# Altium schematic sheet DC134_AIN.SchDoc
size 431 x 279 mm; Date: Not shown in title block; ApprovedBy: Not shown in title block; CheckedBy: Not shown in title block; Author: Not shown in title block; CompanyName: Not shown in title block; Engineer: Not shown in title block; Organization: Not shown in title block; Address1: Not shown in title block; Address2: Not shown in title block; Address3: Not shown in title block; Address4: Not shown in title block; DocumentNumber: 2; Revision: Use project parameter SCH_Rev; SheetNumber: 2; SheetTotal: 9; PageSetup: Record=PageOptions¦CenterHorizontal=True¦CenterVertical=True¦PrintScale=1.00¦XCorrection=1.00¦YCorrection=1.00¦PrintKind=0¦BorderSize=5000000¦LeftOffset=0¦BottomOffset=0¦Orientation=2¦PaperLength=1000¦PaperWidth=1000¦Scale=100¦PaperSource=15¦PrintQuality=600¦MediaType=1¦DitherType=10¦PaperKind=Letter¦PrintScaleMode=1
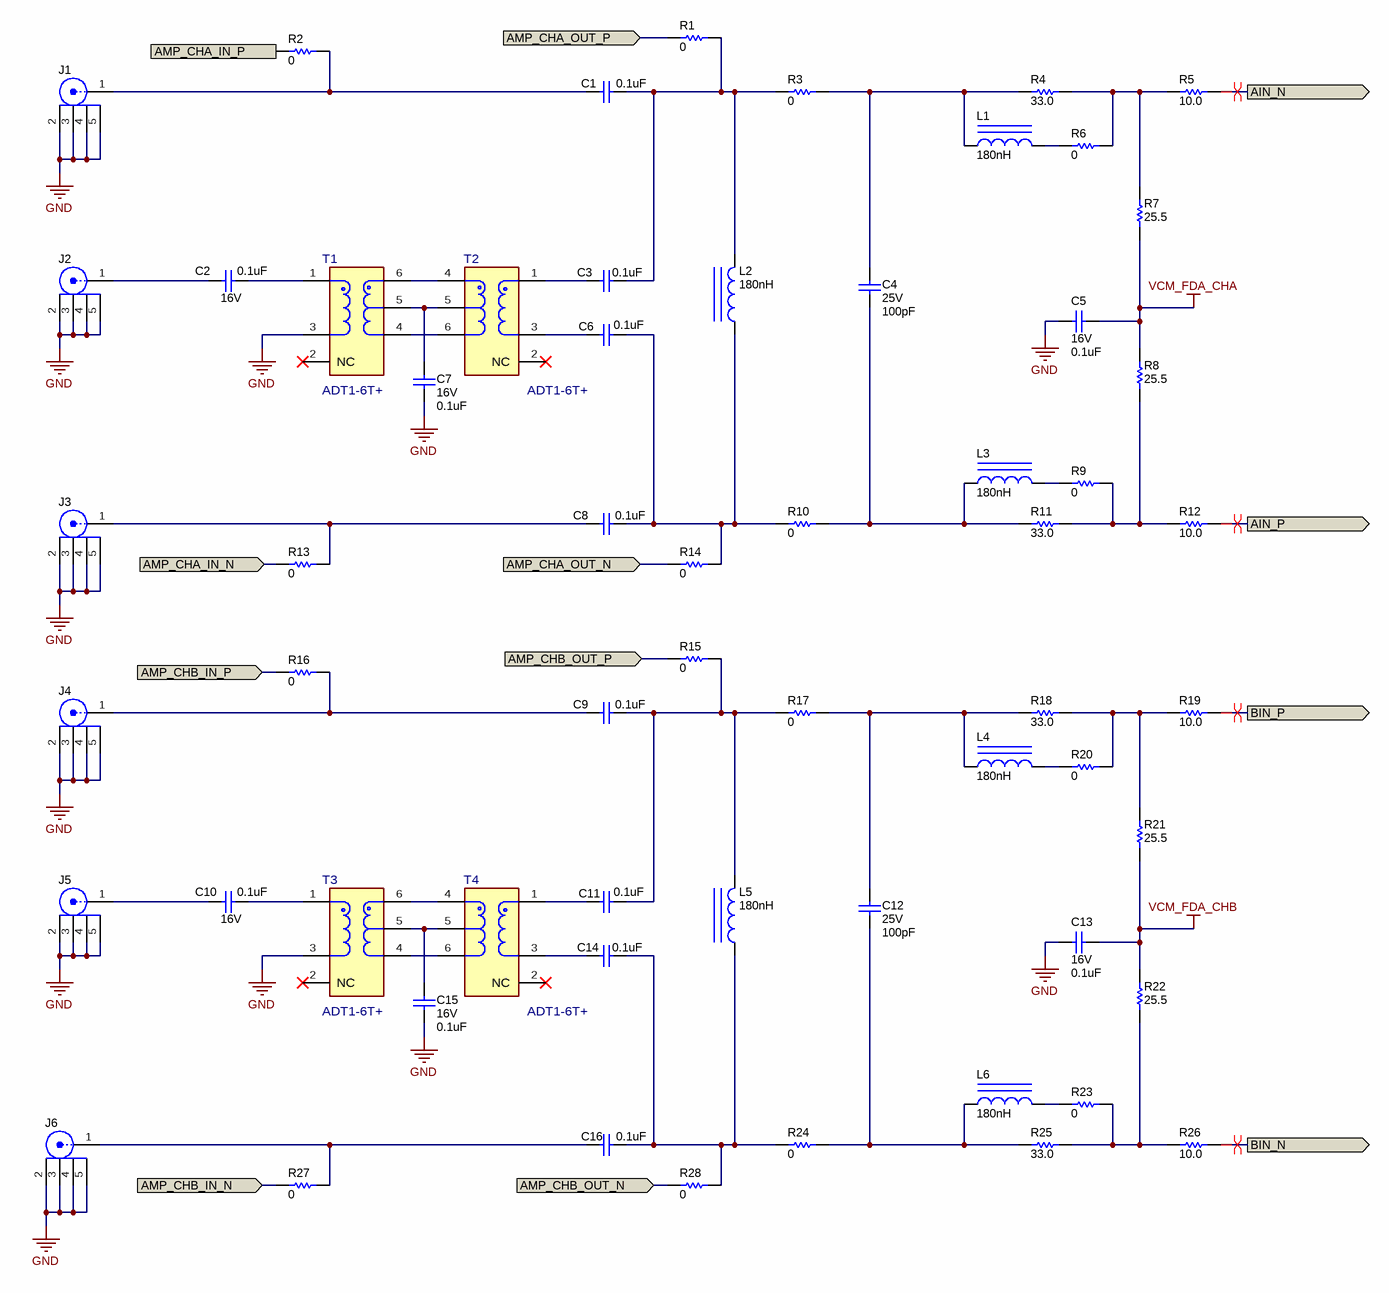
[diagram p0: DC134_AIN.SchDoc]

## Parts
C1  ValueDisplayed: 0.1uF  [0201L]  (hidden comment: GRM033Z71C104KE14D)
C2  VDC_V: 16V  ValueDisplayed: 0.1uF  [0201L]  (hidden comment: GRM033Z71C104KE14D)
C3  ValueDisplayed: 0.1uF  [0201L]  (hidden comment: GRM033Z71C104KE14D)
C4  VDC_V: 25V  ValueDisplayed: 100pF  [0201]  (hidden comment: GRM033R71E101KA01D)
C5  VDC_V: 16V  ValueDisplayed: 0.1uF  [0201L]  (hidden comment: GRM033Z71C104KE14D)
C6  ValueDisplayed: 0.1uF  [0201L]  (hidden comment: GRM033Z71C104KE14D)
C7  VDC_V: 16V  ValueDisplayed: 0.1uF  [0201L]  (hidden comment: GRM033Z71C104KE14D)
C8  ValueDisplayed: 0.1uF  [0201L]  (hidden comment: GRM033Z71C104KE14D)
C9  ValueDisplayed: 0.1uF  [0201L]  (hidden comment: GRM033Z71C104KE14D)
C10  VDC_V: 16V  ValueDisplayed: 0.1uF  [0201L]  (hidden comment: GRM033Z71C104KE14D)
C11  ValueDisplayed: 0.1uF  [0201L]  (hidden comment: GRM033Z71C104KE14D)
C12  VDC_V: 25V  ValueDisplayed: 100pF  [0201]  (hidden comment: GRM033R71E101KA01D)
C13  VDC_V: 16V  ValueDisplayed: 0.1uF  [0201L]  (hidden comment: GRM033Z71C104KE14D)
C14  ValueDisplayed: 0.1uF  [0201L]  (hidden comment: GRM033Z71C104KE14D)
C15  VDC_V: 16V  ValueDisplayed: 0.1uF  [0201L]  (hidden comment: GRM033Z71C104KE14D)
C16  ValueDisplayed: 0.1uF  [0201L]  (hidden comment: GRM033Z71C104KE14D)
J1  142-0701-801  [Johnson_142-0701-801]  (value not drawn)
J2  901-144-8RFX  [AMPHENOL_901-144-8RFX]  (value not drawn)
J3  142-0701-801  [Johnson_142-0701-801]  (value not drawn)
J4  142-0701-801  [Johnson_142-0701-801]  (value not drawn)
J5  901-144-8RFX  [AMPHENOL_901-144-8RFX]  (value not drawn)
J6  142-0701-801  [Johnson_142-0701-801]  (value not drawn)
L1  ValueDisplayed: 180nH  [IND_LQG15H]  (hidden comment: LQG15HSR18J02D)
L2  ValueDisplayed: 180nH  [IND_LQG15H]  (hidden comment: LQG15HSR18J02D)
L3  ValueDisplayed: 180nH  [IND_LQG15H]  (hidden comment: LQG15HSR18J02D)
L4  ValueDisplayed: 180nH  [IND_LQG15H]  (hidden comment: LQG15HSR18J02D)
L5  ValueDisplayed: 180nH  [IND_LQG15H]  (hidden comment: LQG15HSR18J02D)
L6  ValueDisplayed: 180nH  [IND_LQG15H]  (hidden comment: LQG15HSR18J02D)
R1  ValueDisplayed: 0  [0201L]  (hidden comment: CRCW02010000Z0ED)
R2  ValueDisplayed: 0  [0201L]  (hidden comment: CRCW02010000Z0ED)
R3  ValueDisplayed: 0  [0402]  (hidden comment: RC0402JR-070RL)
R4  ValueDisplayed: 33.0  [0201]  (hidden comment: RC0201FR-7D33RL)
R5  ValueDisplayed: 10.0  [0201]  (hidden comment: RC0201FR-7D10RL)
R6  ValueDisplayed: 0  [0201L]  (hidden comment: CRCW02010000Z0ED)
R7  ValueDisplayed: 25.5  [0201L]  (hidden comment: RC0201FR-0725R5L)
R8  ValueDisplayed: 25.5  [0201L]  (hidden comment: RC0201FR-0725R5L)
R9  ValueDisplayed: 0  [0201L]  (hidden comment: CRCW02010000Z0ED)
R10  ValueDisplayed: 0  [0402]  (hidden comment: RC0402JR-070RL)
R11  ValueDisplayed: 33.0  [0201]  (hidden comment: RC0201FR-7D33RL)
R12  ValueDisplayed: 10.0  [0201]  (hidden comment: RC0201FR-7D10RL)
R13  ValueDisplayed: 0  [0201L]  (hidden comment: CRCW02010000Z0ED)
R14  ValueDisplayed: 0  [0201L]  (hidden comment: CRCW02010000Z0ED)
R15  ValueDisplayed: 0  [0201L]  (hidden comment: CRCW02010000Z0ED)
R16  ValueDisplayed: 0  [0201L]  (hidden comment: CRCW02010000Z0ED)
R17  ValueDisplayed: 0  [0402]  (hidden comment: RC0402JR-070RL)
R18  ValueDisplayed: 33.0  [0201]  (hidden comment: RC0201FR-7D33RL)
R19  ValueDisplayed: 10.0  [0201]  (hidden comment: RC0201FR-7D10RL)
R20  ValueDisplayed: 0  [0201L]  (hidden comment: CRCW02010000Z0ED)
R21  ValueDisplayed: 25.5  [0201L]  (hidden comment: RC0201FR-0725R5L)
R22  ValueDisplayed: 25.5  [0201L]  (hidden comment: RC0201FR-0725R5L)
R23  ValueDisplayed: 0  [0201L]  (hidden comment: CRCW02010000Z0ED)
R24  ValueDisplayed: 0  [0402]  (hidden comment: RC0402JR-070RL)
R25  ValueDisplayed: 33.0  [0201]  (hidden comment: RC0201FR-7D33RL)
R26  ValueDisplayed: 10.0  [0201]  (hidden comment: RC0201FR-7D10RL)
R27  ValueDisplayed: 0  [0201L]  (hidden comment: CRCW02010000Z0ED)
R28  ValueDisplayed: 0  [0201L]  (hidden comment: CRCW02010000Z0ED)
T1  ADT1-6T+  [FP-ADT1-6T+_SMD6-MFG]  (value not drawn)
T2  ADT1-6T+  [FP-ADT1-6T+_SMD6-MFG]  (value not drawn)
T3  ADT1-6T+  [FP-ADT1-6T+_SMD6-MFG]  (value not drawn)
T4  ADT1-6T+  [FP-ADT1-6T+_SMD6-MFG]  (value not drawn)

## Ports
AIN_N (out), AIN_P (out), AMP_CHA_IN_N (in), AMP_CHA_IN_P (in), AMP_CHA_OUT_N (in), AMP_CHA_OUT_P (in), AMP_CHB_IN_N (in), AMP_CHB_IN_P (in), AMP_CHB_OUT_N (in), AMP_CHB_OUT_P (in), BIN_N (out), BIN_P (out)

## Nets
GND: C5.1 C7.1 C13.1 C15.1 J1.2 J1.3 J1.4 J1.5 J2.2 J2.3 J2.4 J2.5 J3.2 J3.3 J3.4 J3.5 J4.2 J4.3 J4.4 J4.5 J5.2 J5.3 J5.4 J5.5 J6.2 J6.3 J6.4 J6.5 T1.3 T3.3
VCM_FDA_CHA: C5.2 R7.1 R8.2
VCM_FDA_CHB: C13.2 R21.1 R22.2
AIN_N: R5.2 ; port AIN_N
AIN_P: R12.2 ; port AIN_P
AMP_CHA_IN_N: R13.1 ; port AMP_CHA_IN_N
AMP_CHA_IN_P: R2.1 ; port AMP_CHA_IN_P
AMP_CHA_OUT_N: R14.1 ; port AMP_CHA_OUT_N
AMP_CHA_OUT_P: R1.1 ; port AMP_CHA_OUT_P
AMP_CHB_IN_N: R27.1 ; port AMP_CHB_IN_N
AMP_CHB_IN_P: R16.1 ; port AMP_CHB_IN_P
AMP_CHB_OUT_N: R28.1 ; port AMP_CHB_OUT_N
AMP_CHB_OUT_P: R15.1 ; port AMP_CHB_OUT_P
BIN_N: R26.2 ; port BIN_N
BIN_P: R19.2 ; port BIN_P
NetC1_1: C1.1 J1.1 R2.2
NetC1_2: C1.2 C3.2 L2.2 R1.2 R3.1
NetC2_1: C2.1 J2.1
NetC2_2: C2.2 T1.1
NetC3_1: C3.1 T2.1
NetC4_1: C4.1 L1.1 R3.2 R4.1
NetC4_2: C4.2 L3.1 R10.2 R11.1
NetC6_1: C6.1 T2.3
NetC6_2: C6.2 C8.2 L2.1 R10.1 R14.2
NetC7_2: C7.2 T1.5 T2.5
NetC8_1: C8.1 J3.1 R13.2
NetC9_1: C9.1 J4.1 R16.2
NetC9_2: C9.2 C11.2 L5.2 R15.2 R17.1
NetC10_1: C10.1 J5.1
NetC10_2: C10.2 T3.1
NetC11_1: C11.1 T4.1
NetC12_1: C12.1 L4.1 R17.2 R18.1
NetC12_2: C12.2 L6.1 R24.2 R25.1
NetC14_1: C14.1 T4.3
NetC14_2: C14.2 C16.2 L5.1 R24.1 R28.2
NetC15_2: C15.2 T3.5 T4.5
NetC16_1: C16.1 J6.1 R27.2
NetL1_2: L1.2 R6.1
NetL3_2: L3.2 R9.1
NetL4_2: L4.2 R20.1
NetL6_2: L6.2 R23.1
NetR4_2: R4.2 R5.1 R6.2 R7.2
NetR8_1: R8.1 R9.2 R11.2 R12.1
NetR18_2: R18.2 R19.1 R20.2 R21.2
NetR22_1: R22.1 R23.2 R25.2 R26.1
NetT1_4: T1.4 T2.6
NetT1_6: T1.6 T2.4
NetT3_4: T3.4 T4.6
NetT3_6: T3.6 T4.4

Not connected (* = marked no-connect by the designer): T1 2(NC)*; T2 2(NC)*; T3 2(NC)*; T4 2(NC)*

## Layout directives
differential pair: AIN_N, AIN_P, BIN_N, BIN_P

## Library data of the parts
C1 C3 C6 C8 C9 C11 C14 C16 = CMP-0064970-1: CAP, CERM, 0.1 uF, 16 V,+/- 10%, X7R, 0201; Manufacturer: MuRata; TaMin_C: -55°C; Polarized: N; SizeAreaWB_mm2: 2.08; Value1: Unknown; U/M: EA; Value: 0.1uF; TaMax_C: 125°C; SizeZ_mm: 0.26; SizeX_mm: 0.6; SizeY_mm: 0.3; Cap_Case: 0201; Value2: 16V; SizeArea_mm2: 0.18; CompType: Capacitor; Cap_F: 100nF; AEC Category: Q200
C2 C5 C7 C10 C13 C15 = CMP-0064970-1: CAP, CERM, 0.1 uF, 16 V,+/- 10%, X7R, 0201; Manufacturer: MuRata; TaMin_C: -55°C; Polarized: N; SizeAreaWB_mm2: 2.08; Value1: Unknown; U/M: EA; Value: 0.1uF; TaMax_C: 125°C; SizeZ_mm: 0.26; SizeX_mm: 0.6; SizeY_mm: 0.3; Cap_Case: 0201; SizeArea_mm2: 0.18; CompType: Capacitor; Cap_F: 100nF; AEC Category: Q200
C4 C12 = CMP-0009763-1: CAP, CERM, 100 pF, 25 V, +/- 10%, X7R, 0201; Manufacturer: MuRata; TaMin_C: -55°C; Polarized: N; SizeAreaWB_mm2: 2.08; Value1: Unknown; U/M: EA; Value: 100pF; TaMax_C: 125°C; SizeZ_mm: 0.26; SizeX_mm: 0.6; SizeY_mm: 0.3; SizeArea_mm2: 0.18; AEC Category: Q200
J1 J3 J4 J6 = CMP-0055828-1: Connector, End launch SMA, 50 ohm, SMT; Manufacturer: Cinch Connectivity; CNHeader: FALSE; Green_Lifecycle: Not Set; Green_REACh: Incomplete; CT: TRUE
J2 J5 = CMP-0055833-1: SMA Straight Jack, Gold, 50 Ohm, TH; Manufacturer: Amphenol RF; CNHeader: FALSE; Green_Lifecycle: Not Set; Green_REACh: Incomplete; CT: TRUE
L1-L6 = CMP-0058650-1: Inductor, Multilayer, Air Core, 180 nH, 0.14 A, 3.38 ohm, SMD; Manufacturer: MuRata; Isat: 0.14A @ % inductance drop; Irms: 0.14A @ C rise; Green_Lifecycle: Active; SizeAreaWB_mm2: 3; DCR_ohm: 3.38; Green_REACh: Passed; Value: 180nH; Imax_A: 140mA; SizeZ_mm: 0.55; SizeX_mm: 1; SizeY_mm: 0.5; Value2: 0.14A; AEC Category: Q200
R1 R2 R6 R9 R13-R16 R20 R23 R27 R28 = CMP-0027008-4: RES, 0, 5%, 0.05 W, 0201; Manufacturer: Vishay-Dale; Power_W: 50mW; TempCo: ppm/C; Value_Code: 0000; Value: 0; EIA_Code: E24; SizeX_mm: 0.6; SizeY_mm: 0.3; SizeZ_mm: 0.26; Value2: 0.05W; SizeArea_mm2: 0.18; AEC Qualified: N; AEC Category: Q200
R3 R10 R17 R24 = CMP-0027004-2: RES, 0, 5%, 0.063 W, 0402; Manufacturer: Yageo America; Power_W: 63mW; TempCo: 200 ppm/C; Value_Code: 0000; U/M: EA; Value: 0; EIA_Code: E24; SizeX_mm: 1; SizeY_mm: 0.5; SizeZ_mm: 0.6; Value2: 0.063W; VDC_V: 50V; AEC Category: Q200
R4 R11 R18 R25 = CMP-0028006-1: RES, 33.0, 1%, 0.05 W, 0201; Manufacturer: Yageo America; Power_W: 50mW; TempCo: 200 ppm/C; Value_Code: 33R0; U/M: EA; Value: 33.0; Res_ohm: 33; SizeX_mm: 0.6; SizeY_mm: 0.3; SizeZ_mm: 0.26; Value2: 0.05W; SizeArea_mm2: 0.18; AEC Qualified: N; VDC_V: 25V; AEC Category: Q200
R5 R12 R19 R26 = CMP-0027946-1: RES, 10.0, 1%, 0.05 W, 0201; Manufacturer: Yageo America; Power_W: 50mW; TempCo: 350 ppm/C; Value_Code: 10R0; U/M: EA; Value: 10.0; EIA_Code: E96; Res_ohm: 10; SizeX_mm: 0.6; SizeY_mm: 0.3; SizeZ_mm: 0.26; Value2: 0.05W; SizeArea_mm2: 0.18; AEC Qualified: N; VDC_V: 25V; AEC Category: Q200
R7 R8 R21 R22 = CMP-0027524-1: RES, 25.5, 1%, 0.05 W, 0201; Manufacturer: Yageo America; Power_W: 50mW; TempCo: 200 ppm/C; Value_Code: 25R5; U/M: EA; Value: 25.5; EIA_Code: E96; SizeX_mm: 0.6; SizeY_mm: 0.3; SizeZ_mm: 0.26; Value2: 0.05W; SizeArea_mm2: 0.18; CompType: Resistor; AEC Qualified: N; VDC_V: 25V; AEC Category: Q200
T1-T4 = CMP-0086669-1: Transformer 50Ω/0.03 to 125 MHz; Manufacturer: Mini-Circuits; Rsec1_ohm: 50; Ns1toNp: 1:1; SizeZ_mm: .206inch; AEC Qualified: No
